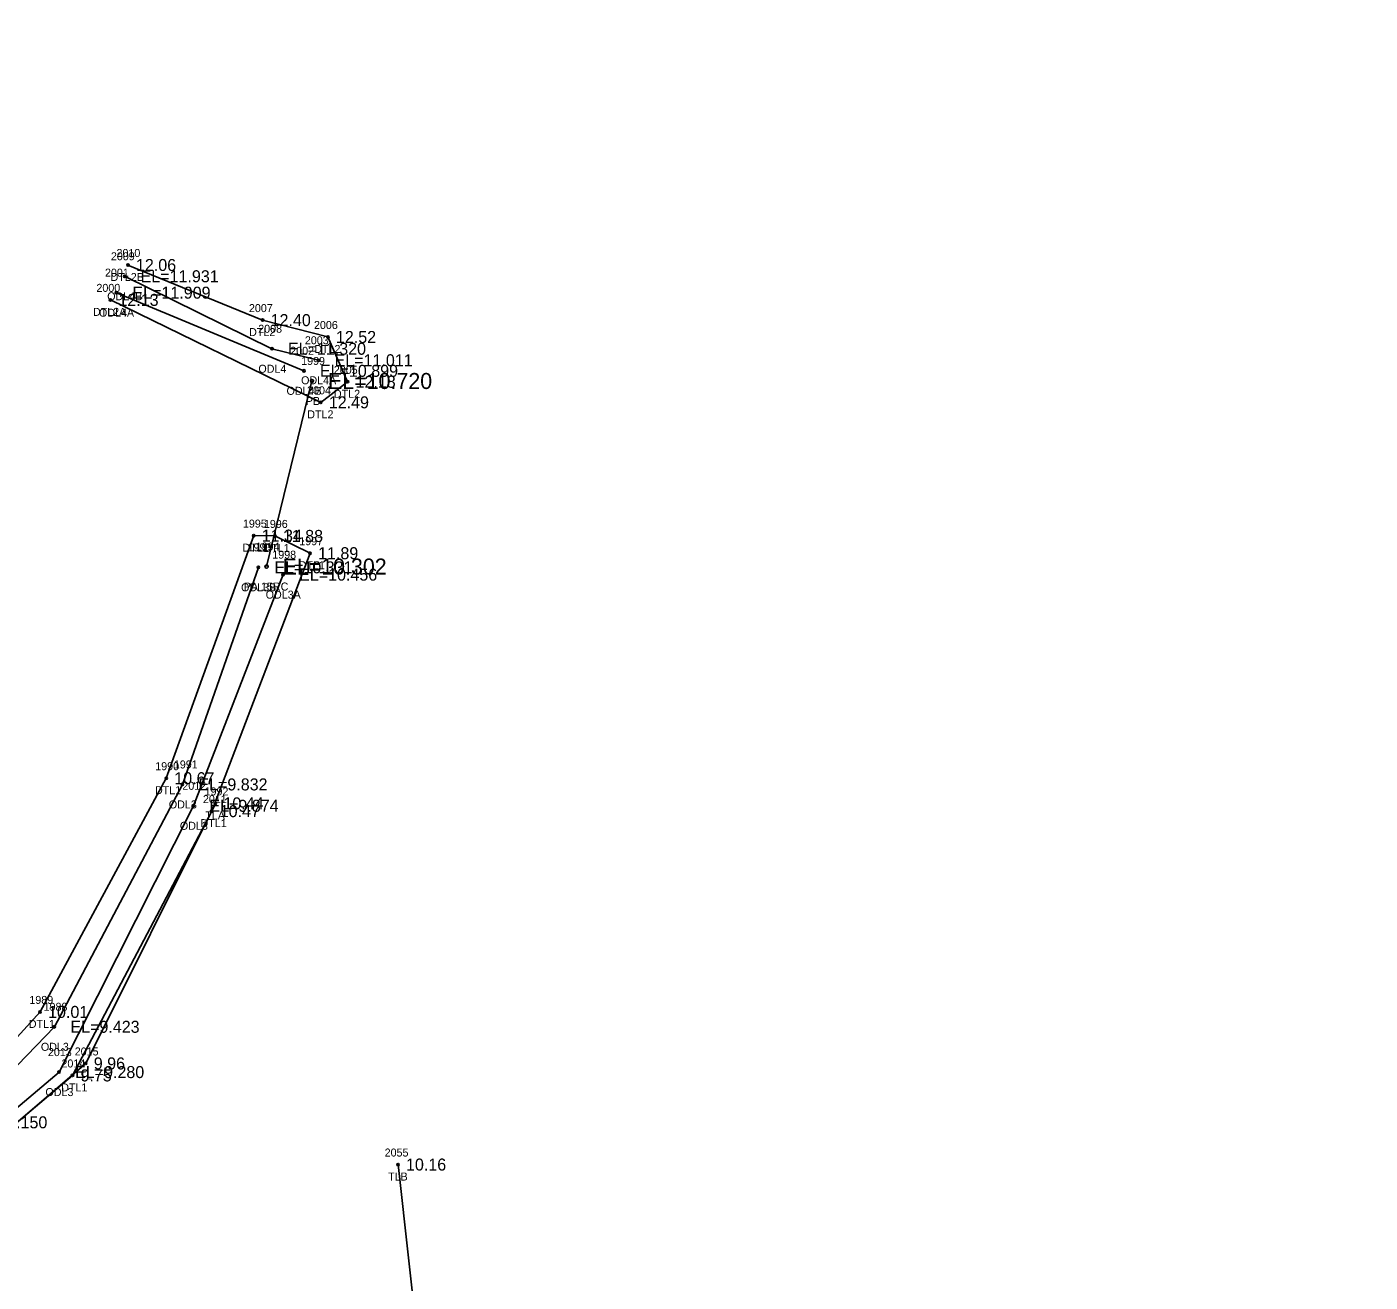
# Model space of a CAD drawing. Extents: x 2042211 to 2045853, y 303080 to 309569.
# Drawn here: x 2044179.7 to 2044347.6, y 305125.9 to 305282.9 of the extents above; entities that cross this region are included whole.
import ezdxf

# ---------------------------------------------------------------- set-up
doc = ezdxf.new("R2010")
doc.units = 0
for name, color, linetype in [('BR_500YR_SCOUR', 7, 'Continuous'), ('RD_EX_DR_Pipe_txCode', 7, 'Continuous'), ('RD_EX_H2O', 7, 'Continuous'), ('RD_EX_H2O_txCode', 7, 'Continuous'), ('RD_EX_TX_H2O_ELEV', 7, 'Continuous'), ('RD_EX_TX_VEG_ELEV', 7, 'Continuous'), ('RD_EX_VEG_txCode', 7, 'Continuous'), ('RD_SMD_Locator', 7, 'Continuous'), ('RD_TX_Pipe_ElevEX', 7, 'Continuous')]:
    doc.layers.add(name, color=color, linetype=linetype)

msp = doc.modelspace()

# ---------------------------------------------------------------- linework, layer by layer
at = {"layer": 'BR_500YR_SCOUR'}
msp.add_line((2044209.68, 305215.41), (2044215.36, 305238.61), dxfattribs=at)
msp.add_lwpolyline([(2044203.29, 305185.8), (2044187.09, 305153.29), (2044169.64, 305138.38), (2044164.21, 305129.35), (2044163.7, 305117.76), (2044206.63, 305057.39), (2044230.52, 305052.69), (2044229.62, 305068.74), (2044231.4, 305092.87), (2044226.11, 305140.65)], dxfattribs=at)
for centre, radius in [((2044215.36, 305238.61), 0.2), ((2044209.68, 305215.41), 0.2), ((2044203.29, 305185.8), 0.15), ((2044187.09, 305153.29), 0.15), ((2044226.11, 305140.65), 0.15)]:
    msp.add_circle(centre, radius, dxfattribs=at)
at = {"layer": 'RD_EX_H2O'}
msp.add_line((2044190.92, 305249.65), (2044214.35, 305239.88), dxfattribs=at)
for points in [[(2043695.41, 305785.95), (2043753.23, 305702.74), (2043816.84, 305621.67), (2043878.98, 305542.47), (2043936.42, 305466.41), (2044001.08, 305383.06), (2044036.64, 305336.24), (2044042.32, 305312.25), (2044044.08, 305296.68), (2044037.04, 305284.58), (2044037.23, 305281.89), (2044040.11, 305279.62), (2044044.74, 305276.06), (2044050.89, 305261.28), (2044092.5, 305206.78), (2044153.45, 305129.2), (2044155.72, 305128.46), (2044158.75, 305129.8), (2044171.64, 305145.93), (2044183.17, 305157.87), (2044199.16, 305188.17), (2044208.66, 305215.31)], [(2044052.64, 305262.28), (2044093.07, 305207.37), (2044155.92, 305130.37), (2044157.38, 305130.75), (2044170.33, 305147.63), (2044181.38, 305159.73), (2044197.15, 305188.95), (2044208.08, 305219.28), (2044210.72, 305219.24), (2044215.12, 305217.08), (2044202.83, 305184.83), (2044185.43, 305151.79), (2044169.6, 305138.4), (2044160.58, 305125.38), (2044211.54, 305068.64), (2044219.9, 305056.44), (2044285.19, 304978.84), (2044339.94, 304911.4), (2044347.53, 304904.82), (2044347.6, 304901.86)], [(2044190.17, 305248.75), (2044216.46, 305235.94), (2044219.8, 305238.51), (2044217.35, 305244.11), (2044209.19, 305246.22), (2044192.36, 305253.11)], [(2044216.18, 305241.2), (2044210.35, 305242.64), (2044191.94, 305251.7)], [(2044211.75, 305214.4), (2044200.54, 305185.5), (2044183.75, 305152.21), (2044168.79, 305139.58), (2044158.66, 305124.96), (2044210.53, 305066.67), (2044218.51, 305055.53), (2044282.21, 304976.06), (2044339.42, 304909.19), (2044345.98, 304903.69)]]:
    msp.add_lwpolyline(points, dxfattribs=at)
at = {"layer": 'RD_SMD_Locator'}
for centre in [(2044192.36, 305253.11), (2044191.94, 305251.7), (2044190.92, 305249.65), (2044190.17, 305248.75), (2044209.19, 305246.22), (2044210.35, 305242.64), (2044217.35, 305244.11), (2044216.18, 305241.2), (2044214.35, 305239.88), (2044219.8, 305238.51), (2044216.46, 305235.94), (2044208.08, 305219.28), (2044210.72, 305219.24), (2044215.12, 305217.08), (2044208.66, 305215.31), (2044211.75, 305214.4), (2044197.15, 305188.95), (2044199.16, 305188.17), (2044200.54, 305185.5), (2044202.83, 305184.83), (2044181.38, 305159.73), (2044183.17, 305157.87), (2044183.75, 305152.21), (2044185.43, 305151.79)]:
    msp.add_circle(centre, 0.15, dxfattribs=at)

# ---------------------------------------------------------------- texts
at = {"layer": 'RD_EX_DR_Pipe_txCode'}
for s, p in [('1999', (2044214.01, 305240.61)), ('PB', (2044214.58, 305235.61)), ('1994', (2044208.33, 305217.41)), ('PA 15RC', (2044206.83, 305212.41))]:
    msp.add_text(s, height=1, dxfattribs=at).set_placement(p)
at = {"layer": 'RD_EX_H2O_txCode'}
for s, p in [('2009', (2044190.23, 305253.7)), ('2010', (2044190.93, 305254.11)), ('2001', (2044189.49, 305251.65)), ('DTL2B', (2044190.19, 305251.11)), ('2000', (2044188.42, 305249.75)), ('ODL4B', (2044189.77, 305248.7)), ('DTL2A', (2044187.99, 305246.75)), ('ODL4A', (2044188.74, 305246.65)), ('2007', (2044207.48, 305247.22)), ('2006', (2044215.61, 305245.11)), ('DTL2', (2044207.5, 305244.22)), ('2008', (2044208.64, 305244.64)), ('2002', (2044212.64, 305241.88)), ('2003', (2044214.47, 305243.2)), ('DTL2', (2044215.65, 305242.11)), ('ODL4', (2044208.66, 305239.64)), ('2005', (2044218.09, 305239.51)), ('ODL4B', (2044212.18, 305236.88)), ('ODL4A', (2044214, 305238.2)), ('2004', (2044214.75, 305236.94)), ('DTL2', (2044218.1, 305236.51)), ('DTL2', (2044214.77, 305233.94)), ('1995', (2044206.73, 305220.28)), ('1996', (2044209.35, 305220.24)), ('1997', (2044213.77, 305218.08)), ('DTL1', (2044206.67, 305217.28)), ('1993', (2044207.31, 305217.31)), ('DTL1', (2044209.31, 305217.24)), ('1998', (2044210.4, 305216.4)), ('DTL1', (2044213.71, 305215.08)), ('ODL3B', (2044206.5, 305212.31)), ('ODL3A', (2044209.57, 305211.4)), ('1990', (2044195.77, 305189.95)), ('1991', (2044198.1, 305190.17)), ('DTL1', (2044195.74, 305186.95)), ('2012', (2044199.16, 305187.5)), ('ODL3', (2044197.47, 305185.17)), ('2011', (2044201.73, 305185.83)), ('ODL3', (2044198.85, 305182.5)), ('DTL1', (2044201.43, 305182.83)), ('1989', (2044180.04, 305160.73)), ('1988', (2044181.82, 305159.87)), ('DTL1', (2044179.97, 305157.73)), ('ODL3', (2044181.48, 305154.87)), ('2013', (2044182.36, 305154.21)), ('2014', (2044184.05, 305152.79)), ('DTL1', (2044184.02, 305149.79)), ('ODL3', (2044182.05, 305149.21))]:
    msp.add_text(s, height=1, dxfattribs=at).set_placement(p)
at = {"layer": 'RD_EX_TX_H2O_ELEV'}
for s, p in [('12.06', (2044193.36, 305252.36)), ('EL=11.931', (2044193.94, 305250.95)), ('12.13', (2044191.17, 305248)), ('EL=11.909', (2044192.92, 305248.9)), ('12.40', (2044210.19, 305245.47)), ('12.52', (2044218.35, 305243.36)), ('EL=11.320', (2044212.35, 305241.89)), ('EL=11.011', (2044218.18, 305240.45)), ('EL=10.899', (2044216.35, 305239.13)), ('12.18', (2044220.8, 305237.76)), ('12.49', (2044217.46, 305235.19)), ('11.34', (2044209.08, 305218.53)), ('11.88', (2044211.72, 305218.49)), ('11.89', (2044216.12, 305216.33)), ('EL=10.331', (2044210.66, 305214.56)), ('EL=10.456', (2044213.75, 305213.65)), ('10.67', (2044198.15, 305188.2)), ('EL=9.832', (2044201.16, 305187.42)), ('EL=9.874', (2044202.54, 305184.75)), ('10.47', (2044203.83, 305184.08)), ('10.01', (2044182.38, 305158.98)), ('EL=9.423', (2044185.17, 305157.12)), ('EL=9.280', (2044185.75, 305151.46)), ('9.75', (2044186.43, 305151.04)), ('EL=9.150', (2044173.64, 305145.18))]:
    msp.add_text(s, height=1.5, dxfattribs=at).set_placement(p)
at = {"layer": 'RD_EX_TX_VEG_ELEV'}
for s, p in [('10.44', (2044204.29, 305185.05)), ('9.96', (2044188.09, 305152.54)), ('10.16', (2044227.11, 305139.9))]:
    msp.add_text(s, height=1.5, dxfattribs=at).set_placement(p)
at = {"layer": 'RD_EX_VEG_txCode'}
for s, p in [('1992', (2044201.94, 305186.8)), ('TLA', (2044202.03, 305183.8)), ('2015', (2044185.71, 305154.29)), ('TL', (2044186.32, 305151.29)), ('2055', (2044224.44, 305141.65)), ('TLB', (2044224.87, 305138.65))]:
    msp.add_text(s, height=1, dxfattribs=at).set_placement(p)
at = {"layer": 'RD_TX_Pipe_ElevEX'}
for s, p in [('EL=10.720', (2044217.36, 305237.61)), ('EL=10.302', (2044211.68, 305214.41))]:
    msp.add_text(s, height=2, dxfattribs=at).set_placement(p)

doc.saveas('drawing.dxf')
